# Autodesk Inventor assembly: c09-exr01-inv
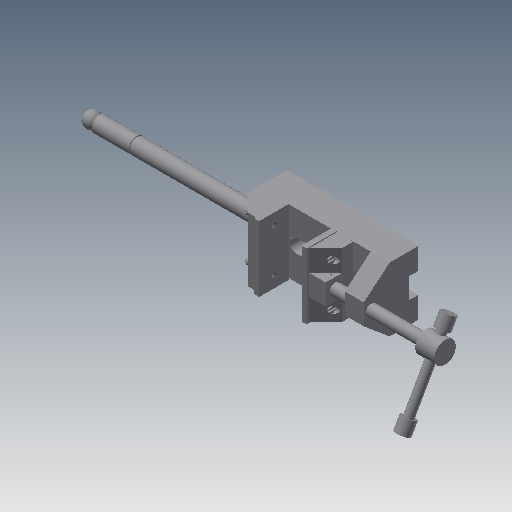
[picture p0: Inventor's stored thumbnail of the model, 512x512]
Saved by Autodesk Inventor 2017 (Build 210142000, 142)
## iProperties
Created: 2011-07
Part Number: c09-exr01-inv
Document SubType Name: Assembly
Designer: CadCim
Author: CadCim
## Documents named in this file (9)
- D:\KAVITA\Autodesk Inventor_2017_Project\Part's File\Inventor_2017_tut\c13_Inv_tut_2017\c13-tut02-inv\Drill Press vice\Drill Press Vice\c09-exr01-inv.iam
- D:\KAVITA\Autodesk Inventor_2017_Project\Part's File\Inventor_2017_tut\c13_Inv_tut_2017\c13-tut02-inv\Drill Press vice\Drill Press Vice\Base.ipt
- D:\KAVITA\Autodesk Inventor_2017_Project\Part's File\Inventor_2017_tut\c13_Inv_tut_2017\c13-tut02-inv\Drill Press vice\Drill Press Vice\Jaw Face.ipt
- D:\KAVITA\Autodesk Inventor_2017_Project\Part's File\Inventor_2017_tut\c13_Inv_tut_2017\c13-tut02-inv\Drill Press vice\Drill Press Vice\Movable Jaw.ipt
- D:\KAVITA\Autodesk Inventor_2017_Project\Part's File\Inventor_2017_tut\c13_Inv_tut_2017\c13-tut02-inv\Drill Press vice\Drill Press Vice\Safety Handle.ipt
- D:\KAVITA\Autodesk Inventor_2017_Project\Part's File\Inventor_2017_tut\c13_Inv_tut_2017\c13-tut02-inv\Drill Press vice\Drill Press Vice\Clamp Screw.ipt
- D:\KAVITA\Autodesk Inventor_2017_Project\Part's File\Inventor_2017_tut\c13_Inv_tut_2017\c13-tut02-inv\Drill Press vice\Drill Press Vice\Clamp Screw Handle.ipt
- D:\KAVITA\Autodesk Inventor_2017_Project\Part's File\Inventor_2017_tut\c13_Inv_tut_2017\c13-tut02-inv\Drill Press vice\Drill Press Vice\Handle Stop.ipt
- D:\KAVITA\Autodesk Inventor_2017_Project\Part's File\Inventor_2017_tut\c13_Inv_tut_2017\c13-tut02-inv\Drill Press vice\Drill Press Vice\Cap Screw.ipt
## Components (13 placed, 8 different names)
1. Base:1 — Insert:3, Insert:9, Insert:10, Mate:8, Mate:9, Mate:12, Mate:13
2. Jaw Face:1 — Mate:10, Mate:11, Mate:12
3. Movable Jaw:1 — Mate:3, Insert:4, Insert:11, Insert:12, Mate:9, Mate:13, Mate:15
4. Safety Handle:1 — Insert:3
5. Clamp Screw:1 — Mate:3, Insert:4, Mate:4, Mate:6, Mate:8
6. Clamp Screw Handle:1 — Mate:4, Insert:7, Insert:8
7. Jaw Face:2 — Mate:14, Mate:15
8. Handle Stop:1 — Insert:7, Mate:6
9. Handle Stop:2 — Insert:8
10. Cap Screw:1 — Insert:12
11. Cap Screw:2 — Insert:11, Mate:14
12. Cap Screw:3 — Insert:10, Mate:11
13. Cap Screw:4 — Insert:9, Mate:10
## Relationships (19: Mate 11, Insert 8)
- Insert:3: Base:1 ↔ Safety Handle:1
- Mate:3: Movable Jaw:1 ↔ Clamp Screw:1
- Insert:4: Movable Jaw:1 ↔ Clamp Screw:1
- Mate:4: Clamp Screw:1 ↔ Clamp Screw Handle:1
- Insert:7: Clamp Screw Handle:1 ↔ Handle Stop:1
- Insert:8: Clamp Screw Handle:1 ↔ Handle Stop:2
- Mate:6: Clamp Screw:1 ↔ Handle Stop:1
- Insert:9: Base:1 ↔ Cap Screw:4
- Insert:10: Base:1 ↔ Cap Screw:3
- Insert:11: Movable Jaw:1 ↔ Cap Screw:2
- Insert:12: Movable Jaw:1 ↔ Cap Screw:1
- Mate:8: Base:1 ↔ Clamp Screw:1
- Mate:9: Base:1 ↔ Movable Jaw:1
- Mate:10: Jaw Face:1 ↔ Cap Screw:4
- Mate:11: Jaw Face:1 ↔ Cap Screw:3
- Mate:12: Base:1 ↔ Jaw Face:1
- Mate:13: Base:1 ↔ Movable Jaw:1
- Mate:14: Jaw Face:2 ↔ Cap Screw:2
- Mate:15: Movable Jaw:1 ↔ Jaw Face:2
